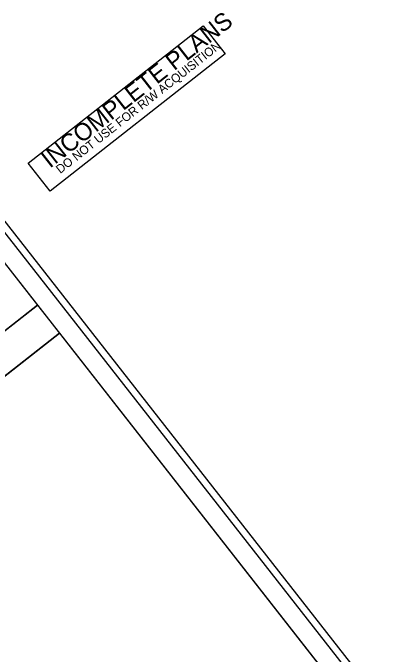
# Model space of a CAD drawing. Extents: x 2176242 to 2178501, y 76147 to 78096.
# Drawn here: x 2177646 to 2177902.7, y 77672.4 to 78095.9 of the extents above; entities that cross this region are included whole.
import ezdxf

# ---------------------------------------------------------------- set-up
doc = ezdxf.new("R2010")
doc.units = 0
for name, color, linetype in [('CTL Primary Horizontal and Vertical CELL', 7, 'Continuous'), ('CTL Primary Horizontal CELL', 7, 'Continuous'), ('CTL Primary Horizontal Cogo Comment', 7, 'Continuous'), ('CTL Primary Horizontal Cogo Number', 7, 'Continuous'), ('Exist Other Culture Sign Cogo Point CELL', 7, 'Continuous'), ('Exist Property Iron Pin CELL', 7, 'Continuous')]:
    doc.layers.add(name, color=color, linetype=linetype)

msp = doc.modelspace()

# ---------------------------------------------------------------- linework, layer by layer
at = {"layer": 'CTL Primary Horizontal and Vertical CELL'}
msp.add_lwpolyline([(2176602.37, 76823.57), (2177301.95, 77811.08), (2177301.95, 77811.08), (2177306.48, 77814.63), (2177363.51, 77741.87), (2177469.29, 77824.79), (2177519.32, 77760.95), (2177676.76, 77884.36), (2178217.46, 77194.57), (2177036.91, 76269.2)], close=True, dxfattribs=at)
at = {"layer": 'CTL Primary Horizontal CELL'}
msp.add_lwpolyline([(2177577.97, 78030.67), (2176266.38, 77002.59), (2176917.29, 76172.19), (2178228.87, 77200.28)], close=True, dxfattribs=at)
at = {"layer": 'CTL Primary Horizontal Cogo Comment'}
for p, q in [((2177504.83, 77779.45), (2177662.26, 77902.85)), ((2177662.27, 77902.84), (2177676.77, 77884.35)), ((2177676.76, 77884.36), (2177519.32, 77760.95))]:
    msp.add_line(p, q, dxfattribs=at)
at = {"layer": 'CTL Primary Horizontal Cogo Number'}
msp.add_lwpolyline([(2177567.66, 78051.12), (2176242.3, 77012.24), (2176920.9, 76146.5), (2178246.26, 77185.38)], close=True, dxfattribs=at)
at = {"layer": 'Exist Other Culture Sign Cogo Point CELL'}
for points in [[(2177569.7, 78020.95), (2176389.16, 77095.58), (2177036.91, 76269.2), (2178217.46, 77194.57)], [(2177514.17, 77929.71), (2177592.87, 77991.4), (2177662.27, 77902.86), (2177583.57, 77841.17)]]:
    msp.add_lwpolyline(points, close=True, dxfattribs=at)
at = {"layer": 'Exist Property Iron Pin CELL'}
msp.add_lwpolyline([(2177670.65, 77978.12), (2177656.16, 77996.62), (2177771.85, 78087.3), (2177786.35, 78068.81)], close=True, dxfattribs=at)

# ---------------------------------------------------------------- texts
for s, height, p in [('INCOMPLETE PLANS', 11.52, (2177670.48, 77992.85)), ('DO NOT USE FOR R/W ACQUISITION', 5.76, (2177677.33, 77989.39))]:
    msp.add_text(s, height=height, rotation=38.091, dxfattribs=at).set_placement(p)

doc.saveas('drawing.dxf')
